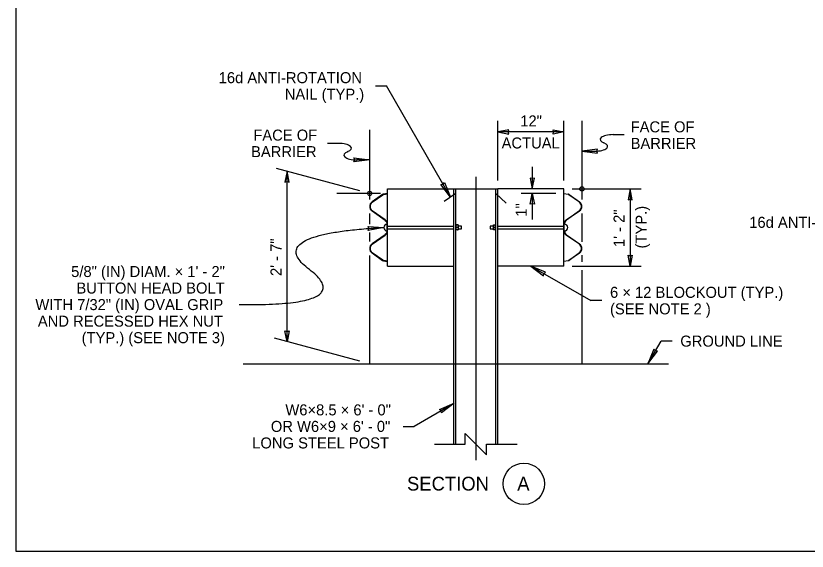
# Model space of a CAD drawing. Extents: x 99862 to 103680, y 99470 to 102076.
# Drawn here: x 99862 to 101011, y 100000 to 100777 of the extents above; entities that cross this region are included whole.
import ezdxf

# ---------------------------------------------------------------- set-up
doc = ezdxf.new("R2010")
doc.units = 0
for name, color, linetype in [('Level 1', 7, 'Continuous'), ('Level 10', 7, 'Continuous'), ('Level 14', 7, 'Continuous'), ('Level 15', 7, 'Continuous'), ('Level 18', 7, 'Continuous'), ('Level 20', 7, 'Continuous'), ('Level 22', 7, 'Continuous'), ('Level 27', 7, 'Continuous'), ('Level 3', 7, 'Continuous'), ('Level 4', 7, 'Continuous'), ('Level 60', 7, 'Continuous'), ('Level 7', 7, 'Continuous'), ('Level 8', 7, 'Continuous')]:
    doc.layers.add(name, color=color, linetype=linetype)

msp = doc.modelspace()

# ---------------------------------------------------------------- linework, layer by layer
at = {"layer": 'Level 1'}
msp.add_lwpolyline([(99862, 99999.5), (103151, 99999.5), (103151, 102075.5), (99862, 102075.5)], close=True, dxfattribs=at)
at = {"layer": 'Level 10'}
for p, q in [((100401.7, 100525.3), (100497.7, 100525.3)), ((100401.7, 100413.3), (100401.7, 100525.3)), ((100657.7, 100525.3), (100561.7, 100525.3)), ((100657.7, 100413.3), (100657.7, 100525.3)), ((100401.7, 100413.3), (100497.7, 100413.3)), ((100657.7, 100413.3), (100561.7, 100413.3))]:
    msp.add_line(p, q, dxfattribs=at)
at = {"layer": 'Level 14'}
msp.add_line((100529.7, 100542.7), (100529.7, 100131.5), dxfattribs=at)
at = {"layer": 'Level 15'}
for p, q in [((100384.1, 100674.8), (100400.1, 100674.8)), ((100493.2, 100513.5), (100400.1, 100674.8)), ((100728.9, 100604.1), (100744.9, 100604.1)), ((100330.6, 100591.4), (100314.6, 100591.4)), ((100683.7, 100580.1), (100702.5, 100580.1)), ((100375.7, 100567.4), (100357, 100567.4)), ((100361.2, 100522.7), (100240.3, 100555.1)), ((100611.7, 100557.3), (100611.7, 100525.3)), ((100255.7, 100365.6), (100255.7, 100550.9)), ((100391.5, 100518.8), (100328.2, 100518.8)), ((100611.7, 100518.8), (100611.7, 100480.8)), ((100609.7, 100413.3), (100696.6, 100363.2)), ((100255.7, 100303.5), (100255.7, 100365.6)), ((100712.6, 100363.2), (100696.6, 100363.2)), ((100186.4, 100357.4), (100202.4, 100357.4)), ((100361.2, 100275.3), (100237.3, 100308.5)), ((100779.5, 100271.4), (100798.6, 100304.4)), ((100814.6, 100304.4), (100798.6, 100304.4)), ((100497.7, 100213.8), (100440.2, 100180.6)), ((100424.2, 100180.6), (100440.2, 100180.6))]:
    msp.add_line(p, q, dxfattribs=at)
for points in [[(100683.7, 100580.1), (100706.6, 100577.2), (100705.5, 100580.2), (100706.6, 100583.2)], [(100375.7, 100567.4), (100352.9, 100564.6), (100354, 100567.5), (100352.9, 100570.5)], [(100255.7, 100550.9), (100252.7, 100535.2), (100255.7, 100535.9), (100258.8, 100535.2)], [(100493.2, 100513.5), (100479.2, 100531.8), (100482.3, 100532.4), (100484.3, 100534.8)], [(100611.7, 100525.3), (100614.8, 100541.1), (100611.7, 100540.3), (100608.7, 100541.1)], [(100611.7, 100518.8), (100614.8, 100503), (100611.7, 100503.8), (100608.7, 100503)], [(100396.2, 100469.3), (100373.7, 100464.9), (100374.5, 100467.9), (100373.3, 100470.8)], [(100609.7, 100413.3), (100628, 100399.3), (100628.6, 100402.5), (100631, 100404.5)], [(100255.7, 100303.5), (100252.7, 100319.3), (100255.7, 100318.5), (100258.8, 100319.3)], [(100779.5, 100271.4), (100793.5, 100289.7), (100790.4, 100290.2), (100788.4, 100292.6)], [(100498.4, 100214.1), (100480.1, 100200.1), (100479.6, 100203.2), (100477.1, 100205.2)]]:
    msp.add_lwpolyline(points, close=True, dxfattribs=at)
msp.add_lwpolyline([(100469.7, 100154.8), (100514.3, 100154.8), (100514.3, 100170.3), (100545.2, 100139.3), (100545.2, 100154.8), (100589.7, 100154.8)], dxfattribs=at)
for centre in [(100375.7, 100518.8), (100683.7, 100525.3)]:
    msp.add_circle(centre, 3.08, dxfattribs=at)
for centre, major_axis, start_param, end_param in [((100729, 100597.1), (-18.7, 0), 4.705244, 7.068624), ((100330.5, 100584.4), (18.7, 0), 5.497747, 7.861127), ((100702.5, 100587.1), (-18.7, 0), 1.570796, 3.926959), ((100357, 100574.4), (18.7, 0), 2.356226, 4.712389)]:
    msp.add_ellipse(centre, major_axis=major_axis, ratio=0.375, start_param=start_param, end_param=end_param, dxfattribs=at)
msp.add_open_spline([(100202.4, 100357.4), (100354.9, 100357.4), (100220.3, 100460.1), (100396.2, 100469.3)], degree=2, dxfattribs=at)
at = {"layer": 'Level 18'}
for p, q in [((100500.7, 100518.8), (100484, 100507.2)), ((100558.7, 100518.8), (100573.7, 100504.5))]:
    msp.add_line(p, q, dxfattribs=at)
for centre, start, end in [((100401.2, 100469.3), 90.1907, 269.8083), ((100658.2, 100469.3), 270.1917, 89.8093)]:
    msp.add_arc(centre, 5, start, end, dxfattribs=at)
at = {"layer": 'Level 20'}
msp.add_circle((100599.5, 100097.3), 30, dxfattribs=at)
at = {"layer": 'Level 22'}
for p, q in [((100561.7, 100537.3), (100561.7, 100624)), ((100657.7, 100537.3), (100657.7, 100624)), ((100683.7, 100624), (100683.7, 100510.1)), ((100375.7, 100510.1), (100375.7, 100611.3)), ((100657.7, 100608), (100561.7, 100608)), ((100669.7, 100525.3), (100769.7, 100525.3)), ((100753.7, 100525.3), (100753.7, 100413.3)), ((100645.7, 100518.8), (100595.7, 100518.8)), ((100375.7, 100474.1), (100375.7, 100489.6)), ((100683.7, 100489.6), (100683.7, 100448.5)), ((100375.7, 100449.1), (100375.7, 100462)), ((100375.7, 100271.4), (100375.7, 100428.6)), ((100683.7, 100429.2), (100683.7, 100419.3)), ((100669.7, 100413.3), (100769.7, 100413.3)), ((100683.7, 100407.3), (100683.7, 100377.6)), ((100683.7, 100379.4), (100683.7, 100271.4))]:
    msp.add_line(p, q, dxfattribs=at)
for points in [[(100561.7, 100608), (100577.5, 100604.9), (100576.7, 100608), (100577.5, 100611.1)], [(100657.7, 100608), (100642, 100604.9), (100642.7, 100608), (100642, 100611.1)], [(100753.7, 100525.3), (100750.7, 100509.6), (100753.7, 100510.3), (100756.8, 100509.6)], [(100753.7, 100413.3), (100750.7, 100429.1), (100753.7, 100428.3), (100756.8, 100429.1)]]:
    msp.add_lwpolyline(points, close=True, dxfattribs=at)
at = {"layer": 'Level 27'}
for p, q in [((100394.4, 100517.1), (100379.1, 100506.4)), ((100379.4, 100506), (100394.7, 100516.7)), ((100401.7, 100518.8), (100395.8, 100517.7)), ((100395.9, 100517.2), (100401.7, 100518.3)), ((100657.7, 100518.8), (100663.7, 100517.7)), ((100663.6, 100517.2), (100657.7, 100518.3)), ((100680.1, 100506), (100664.8, 100516.7)), ((100665.1, 100517.1), (100680.3, 100506.4)), ((100379.1, 100493.3), (100398.1, 100480)), ((100398.3, 100480.4), (100379.4, 100493.7)), ((100661.1, 100480.4), (100680.1, 100493.7)), ((100680.3, 100493.3), (100661.4, 100480)), ((100401.2, 100464.8), (100401.2, 100473.8)), ((100658.2, 100464.8), (100658.2, 100473.8)), ((100398.1, 100458.7), (100379.1, 100445.4)), ((100379.4, 100445), (100398.3, 100458.3)), ((100680.1, 100445), (100661.1, 100458.3)), ((100661.4, 100458.7), (100680.3, 100445.4)), ((100379.1, 100432.3), (100394.4, 100421.6)), ((100394.7, 100422), (100379.4, 100432.7)), ((100664.8, 100422), (100680.1, 100432.7)), ((100680.3, 100432.3), (100665.1, 100421.6)), ((100395.8, 100421), (100401.7, 100419.9)), ((100401.7, 100420.4), (100395.9, 100421.5)), ((100657.7, 100420.4), (100663.6, 100421.5)), ((100663.7, 100421), (100657.7, 100419.9))]:
    msp.add_line(p, q, dxfattribs=at)
for centre, radius, start, end in [((100396.4, 100514.3), 3.5, 100, 125.148), ((100396.4, 100514.3), 3, 100, 125.148), ((100663.1, 100514.3), 3, 54.852, 80), ((100663.1, 100514.3), 3.5, 54.852, 80), ((100383.7, 100499.8), 8, 125.1622, 234.8539), ((100383.7, 100499.8), 7.5, 125.1622, 234.8539), ((100675.7, 100499.8), 7.5, 305.1461, 54.8378), ((100675.7, 100499.8), 8, 305.1461, 54.8378), ((100393.7, 100473.8), 7.5, 0, 54.8388), ((100393.7, 100473.8), 8, 0.0015, 54.8388), ((100665.7, 100473.8), 8, 125.1612, 179.9985), ((100665.7, 100473.8), 7.5, 125.1612, 180), ((100393.7, 100464.8), 7.5, 305.1612, 359.9897), ((100393.7, 100464.8), 8, 305.1612, 359.9897), ((100665.7, 100464.8), 8, 180.0103, 234.8388), ((100665.7, 100464.8), 7.5, 180.0103, 234.8388), ((100383.7, 100438.8), 8, 125.1431, 234.8574), ((100383.7, 100438.8), 7.5, 125.1431, 234.8574), ((100675.7, 100438.8), 7.5, 305.1426, 54.8569), ((100675.7, 100438.8), 8, 305.1426, 54.8569), ((100396.4, 100424.4), 3.5, 234.8563, 260), ((100396.4, 100424.4), 3, 234.8563, 260), ((100663.1, 100424.4), 3, 280, 305.1437), ((100663.1, 100424.4), 3.5, 280, 305.1437)]:
    msp.add_arc(centre, radius, start, end, dxfattribs=at)
at = {"layer": 'Level 3'}
msp.add_line((100500.7, 100463.4), (100500.7, 100475.4), dxfattribs=at)
at = {"layer": 'Level 4'}
for p, q in [((100497.7, 100525.3), (100561.7, 100525.3)), ((100497.7, 100271.4), (100497.7, 100525.3)), ((100500.7, 100271.4), (100500.7, 100525.3)), ((100558.7, 100271.4), (100558.7, 100525.3)), ((100561.7, 100271.4), (100561.7, 100525.3)), ((100497.7, 100154.8), (100497.7, 100271.4)), ((100500.8, 100154.8), (100500.8, 100271.4)), ((100558.7, 100154.8), (100558.7, 100271.4)), ((100561.7, 100154.8), (100561.7, 100271.4))]:
    msp.add_line(p, q, dxfattribs=at)
at = {"layer": 'Level 60'}
msp.add_line((99862, 99999.5), (99862, 99999.5), dxfattribs=at)
at = {"layer": 'Level 7'}
for p, q in [((100500.8, 100473.1), (100500.7, 100473)), ((100503.2, 100473.1), (100501.6, 100473.1)), ((100504.1, 100473), (100504, 100473.1)), ((100504.1, 100473), (100504.1, 100467.7)), ((100555.4, 100473), (100555.5, 100473.1)), ((100555.4, 100467.7), (100555.4, 100473)), ((100556.3, 100473.1), (100557.9, 100473.1)), ((100558.6, 100473.1), (100558.7, 100473)), ((100401.7, 100471.3), (100497.7, 100471.3)), ((100401.7, 100467.3), (100497.7, 100467.3)), ((100500.7, 100465.9), (100500.8, 100465.8)), ((100503.2, 100469.4), (100501.6, 100469.4)), ((100503.2, 100465.8), (100501.6, 100465.8)), ((100504, 100465.8), (100504.1, 100465.9)), ((100508.9, 100471.3), (100504.1, 100471.3)), ((100504.1, 100467.7), (100504.1, 100465.9)), ((100504.1, 100467.6), (100508.9, 100467.6)), ((100508.9, 100467.6), (100508.9, 100471.3)), ((100555.4, 100471.3), (100550.6, 100471.3)), ((100550.6, 100471.3), (100550.6, 100467.6)), ((100550.6, 100467.6), (100555.4, 100467.6)), ((100555.4, 100465.9), (100555.4, 100467.7)), ((100555.5, 100465.8), (100555.4, 100465.9)), ((100556.3, 100469.4), (100557.9, 100469.4)), ((100557.9, 100465.8), (100556.3, 100465.8)), ((100558.7, 100465.9), (100558.6, 100465.8)), ((100561.7, 100471.3), (100658.2, 100471.3)), ((100561.7, 100467.3), (100658.2, 100467.3))]:
    msp.add_line(p, q, dxfattribs=at)
for points, degree in [([(100500.8, 100473.1), (100500.8, 100473.1), (100501.2, 100473.1), (100501.6, 100473.1)], 2), ([(100501.6, 100473.1), (100501.2, 100472.6), (100500.8, 100471.9), (100500.8, 100470.6), (100501.2, 100470), (100501.6, 100469.4)], 3), ([(100504, 100473.1), (100504, 100473.1), (100503.6, 100473.1), (100503.2, 100473.1)], 2), ([(100503.2, 100473.1), (100503.6, 100472.6), (100504, 100471.9), (100504, 100470.6), (100503.6, 100470), (100503.2, 100469.4)], 3), ([(100555.5, 100473.1), (100555.5, 100473.1), (100555.9, 100473.1), (100556.3, 100473.1)], 2), ([(100556.3, 100473.1), (100555.9, 100472.6), (100555.5, 100471.9), (100555.5, 100470.6), (100555.9, 100470), (100556.3, 100469.4)], 3), ([(100557.9, 100473.1), (100558.3, 100473.1), (100558.6, 100473.1), (100558.6, 100473.1)], 2), ([(100557.9, 100469.4), (100558.3, 100470), (100558.6, 100470.6), (100558.6, 100471.9), (100558.3, 100472.6), (100557.9, 100473.1)], 3), ([(100501.6, 100469.4), (100501.2, 100468.9), (100500.8, 100468.3), (100500.8, 100467), (100501.2, 100466.3), (100501.6, 100465.8)], 3), ([(100501.6, 100465.8), (100501.2, 100465.8), (100500.8, 100465.8), (100500.8, 100465.8), (100500.8, 100465.8), (100500.8, 100465.8)], 3), ([(100503.2, 100469.4), (100503.6, 100468.9), (100504, 100468.3), (100504, 100467), (100503.6, 100466.3), (100503.2, 100465.8)], 3), ([(100503.2, 100465.8), (100503.6, 100465.8), (100504, 100465.8), (100504, 100465.8), (100504, 100465.8), (100504, 100465.8)], 3), ([(100556.3, 100469.4), (100555.9, 100468.9), (100555.5, 100468.3), (100555.5, 100467), (100555.9, 100466.3), (100556.3, 100465.8)], 3), ([(100556.3, 100465.8), (100555.9, 100465.8), (100555.5, 100465.8), (100555.5, 100465.8), (100555.5, 100465.8), (100555.5, 100465.8)], 3), ([(100557.9, 100465.8), (100558.3, 100466.3), (100558.6, 100467), (100558.6, 100468.3), (100558.3, 100468.9), (100557.9, 100469.4)], 3), ([(100558.6, 100465.8), (100558.6, 100465.8), (100558.6, 100465.8), (100558.6, 100465.8), (100558.3, 100465.8), (100557.9, 100465.8)], 3)]:
    msp.add_open_spline(points, degree=degree, dxfattribs=at)
at = {"layer": 'Level 8'}
msp.add_line((100192.1, 100271.4), (100809.5, 100271.4), dxfattribs=at)

# ---------------------------------------------------------------- texts
at = {"layer": 'Level 20'}
for s, height, p in [('16d ANTI-ROTATION', 16, (100156.5, 100678.8)), ('NAIL (TYP.)', 16, (100252.4, 100654.8)), ('FACE OF', 16, (100206.8, 100595.4)), ('BARRIER', 16, (100203.5, 100571.4)), ('16d ANTI-ROTATION', 16, (100926.7, 100468.8)), ('5/8" (IN) DIAM. × 1\' - 2"', 16, (99942.3, 100397.4)), ('BUTTON HEAD BOLT', 16, (99950, 100373.4)), ('6 × 12 BLOCKOUT (TYP.)', 16, (100724.6, 100367.2)), ('WITH 7/32" (IN) OVAL GRIP', 16, (99890.4, 100349.4)), ('(SEE NOTE 2', 16, (100724.6, 100343.2)), (')', 16, (100863.7, 100343.2)), ('AND RECESSED HEX NUT', 16, (99894, 100325.4)), (' (TYP.) (SEE NOTE 3)', 16, (99951.6, 100301.4)), ('W6×8.5 × 6\' - 0" ', 16, (100253.3, 100196.6)), ('OR W6×9 × 6\' - 0"', 16, (100232.2, 100172.6)), ('LONG STEEL POST', 16, (100205.2, 100148.6)), ('SECTION', 20, (100429.9, 100087.5)), ('A', 20, (100589.9, 100087.5))]:
    msp.add_text(s, height=height, dxfattribs=at).set_placement(p)
for s, rotation, p in [('12"', 360, (100594.3, 100616)), ('FACE OF', 360, (100754.5, 100607.4)), ('ACTUAL', 360, (100567.2, 100584)), ('BARRIER', 360, (100754.5, 100583.4)), ('1"', 90, (100603.7, 100485)), ('(TYP.)', 90, (100777.7, 100438.9)), ('1\' - 2"', 90, (100745.7, 100441)), ('2\' - 7"', 90, (100247.7, 100398.9)), ('GROUND LINE', 360, (100826.6, 100296.4))]:
    msp.add_text(s, height=16, rotation=rotation, dxfattribs=at).set_placement(p)

doc.saveas('drawing.dxf')
